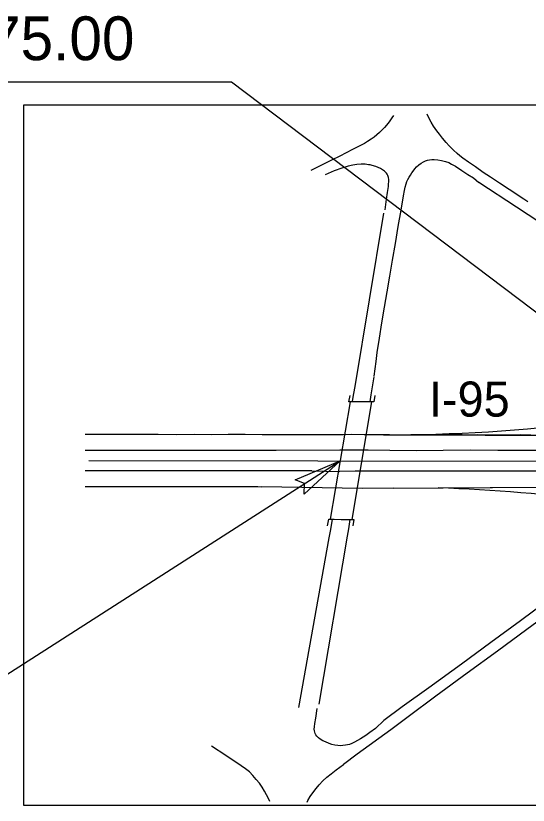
# Model space of a CAD drawing. Extents: x 2241278 to 2254132, y 649924 to 670434.
# Drawn here: x 2247319 to 2248087, y 662535 to 663719 of the extents above; entities that cross this region are included whole.
import ezdxf

# ---------------------------------------------------------------- set-up
doc = ezdxf.new("R2010")
doc.units = 0
for name, color, linetype in [('Pattern 4', 7, 'Continuous'), ('Pattern 6', 7, 'Continuous'), ('Prop DSN Text', 7, 'Continuous'), ('Prop Horizontal Alignment', 7, 'Continuous'), ('Prop RDY Alternate Text Yellow', 7, 'Continuous'), ('Prop Shade Heavy', 7, 'Continuous'), ('Prop Terminator CELL', 7, 'Continuous')]:
    doc.layers.add(name, color=color, linetype=linetype)

msp = doc.modelspace()

# ---------------------------------------------------------------- linework, layer by layer
at = {"layer": 'Pattern 4'}
for p, q in [((2248005.2, 663476.3), (2248013.5, 663469.4)), ((2247709.4, 663067.8), (2247804.9, 663068.4)), ((2247762.8, 663036.7), (2247804.9, 663036.1)), ((2247858.5, 662650.7), (2247870.8, 662662.3))]:
    msp.add_line(p, q, dxfattribs=at)
for points in [[(2247885.4, 663569.9), (2247883.1, 663566.4), (2247878.8, 663560.1), (2247874.9, 663555.4), (2247871.7, 663551.5), (2247867.8, 663547.5), (2247864.3, 663544), (2247860.6, 663540.6), (2247856.4, 663537.3), (2247852, 663534.1), (2247846.5, 663530.6), (2247842, 663527.9), (2247823.9, 663518.6), (2247804.8, 663508.9), (2247792.6, 663503), (2247782.4, 663498), (2247770.4, 663492), (2247761.3, 663487.5)], [(2248086.8, 663440.4), (2248080.8, 663444.4), (2248059.1, 663458.6), (2248044.5, 663468.3), (2248030.8, 663477.3), (2248020.1, 663484.5), (2248008.5, 663492.6), (2247998, 663499.7), (2247989.6, 663505.6), (2247984.9, 663509.2), (2247980.7, 663512.9), (2247975.2, 663518), (2247968.9, 663524.3), (2247964.2, 663529.5), (2247959.1, 663535.7), (2247954.2, 663541.5), (2247950.3, 663546.8), (2247945.5, 663553.8), (2247942, 663559.5), (2247938.9, 663565.4), (2247936.1, 663571.5), (2247936, 663571.8)], [(2247856.6, 663178.7), (2247859.5, 663200.9), (2247860.8, 663214.2), (2247864.2, 663236), (2247868.1, 663258.9), (2247872, 663282.4), (2247876, 663305.1), (2247879.9, 663328.7), (2247884.1, 663352.7), (2247888.2, 663377.9), (2247892.6, 663403.1), (2247896.9, 663427.8), (2247900.6, 663449.3), (2247902.1, 663457.5), (2247902.9, 663462.2), (2247904.2, 663467.3), (2247905.6, 663470.9), (2247907.1, 663474), (2247908.8, 663477.1), (2247910.7, 663480.5), (2247912.8, 663483.7), (2247915, 663486.4), (2247917.3, 663489.7), (2247920.1, 663492.9), (2247923.2, 663495.8), (2247926.7, 663498.3), (2247930.5, 663500.5), (2247933.3, 663501.9), (2247936.2, 663502.9), (2247939.4, 663503.5), (2247942.8, 663503.8), (2247946.2, 663503.8), (2247951.8, 663503.2), (2247957.3, 663502.1), (2247963.6, 663500.9), (2247968.4, 663499.1), (2247972.6, 663497), (2247978.2, 663493.9), (2247987.8, 663487.4), (2247997.1, 663481.1), (2248005.2, 663476.3)], [(2247872.7, 663428.5), (2247875, 663444.3), (2247876.5, 663454.2), (2247877.7, 663463.2), (2247878.1, 663467), (2247878.3, 663471), (2247878.3, 663473.8), (2247877.7, 663476.7), (2247876.9, 663479.6), (2247875.9, 663481.8), (2247875, 663483.1), (2247874, 663484.2), (2247871.8, 663486.5), (2247868.9, 663488.5), (2247865.9, 663490.2), (2247862.2, 663491.9), (2247858.9, 663493.1), (2247853.3, 663494.9), (2247850.3, 663495.6), (2247847.8, 663496), (2247842.8, 663496.8), (2247836.9, 663496.9), (2247830.6, 663496.4), (2247824.3, 663495.4), (2247817.2, 663493.7), (2247808.1, 663491), (2247796.3, 663486.8), (2247782.7, 663481)], [(2248329.4, 663262.5), (2248284.1, 663292), (2248247.5, 663316), (2248175.8, 663363.1), (2248120.9, 663398.9), (2248069.7, 663432.4), (2248013.5, 663469.4)], [(2247870.4, 663423.3), (2247827.2, 663163.3), (2247825.5, 663152.9), (2247823.6, 663141.4)], [(2247850.2, 663140.4), (2247851.9, 663151), (2247853.9, 663162.8), (2247856.4, 663177.8)], [(2247807.9, 663091.1), (2247784.8, 663091.1), (2247761.5, 663091.1), (2247738, 663091.1), (2247713.3, 663091.1), (2247688.4, 663091.1), (2247663, 663091.2), (2247637.6, 663091.2), (2247612.2, 663091.1), (2247586.3, 663091.2), (2247559.6, 663091.1), (2247532.4, 663091.3), (2247504.8, 663091.3), (2247475.9, 663091.3), (2247446.7, 663091.3), (2247423, 663091.2)], [(2247810.3, 663091.1), (2247807.9, 663091.1)], [(2248091.3, 663090.5), (2248076.6, 663090.7), (2248064.7, 663090.6), (2248055.2, 663090.3), (2248047, 663090.5), (2248033.8, 663090.5), (2248023, 663090.6), (2248011.1, 663090.7), (2248001.4, 663090.6), (2247988.3, 663090.7), (2247977.7, 663090.9), (2247969.5, 663090.8), (2247955.6, 663090.8), (2247940.8, 663090.9), (2247925.9, 663090.8), (2247911.6, 663091), (2247897.8, 663090.6), (2247879.4, 663090.8), (2247858.8, 663090.7), (2247841.2, 663091.1), (2247822.3, 663091.3), (2247810.3, 663091.1)], [(2247423.1, 663067.9), (2247443.6, 663067.8), (2247476.3, 663067.9), (2247509.2, 663067.9), (2247542.1, 663068), (2247575.5, 663067.8), (2247609.3, 663067.8), (2247642.9, 663067.8), (2247676.2, 663067.9), (2247709.4, 663067.8)], [(2247804.9, 663068.4), (2247847.2, 663068.4), (2247879.7, 663067.8), (2247919.8, 663067.6), (2247960.1, 663068.1), (2248001.5, 663068.2), (2248042, 663067.9), (2248081, 663067.9), (2248120.5, 663067.8)], [(2247762.8, 663036.7), (2247728.3, 663036.8), (2247698.4, 663036.8), (2247667.2, 663036.8), (2247636.6, 663036.8), (2247606.5, 663036.8), (2247574.8, 663037), (2247543.3, 663036.9), (2247510.7, 663037), (2247481.5, 663037), (2247453.4, 663037.1), (2247431.9, 663037), (2247423, 663037.1)], [(2248112.1, 663036.5), (2248065.5, 663036.6), (2248029.4, 663036.6), (2247990.8, 663036.4), (2247952.3, 663036.6), (2247910.4, 663036.3), (2247868.7, 663036.5), (2247827.7, 663036.5), (2247804.9, 663036.1)], [(2247422.9, 663013.5), (2247431.7, 663013.5), (2247466.8, 663013.4), (2247501.9, 663013.3), (2247537.2, 663013.3), (2247572.2, 663013.2), (2247607.9, 663013.4), (2247643.9, 663013.3), (2247681.7, 663013.3), (2247687.6, 663012.7)], [(2247885.2, 663010.9), (2247839, 663010.3), (2247687.6, 663012.7)], [(2247885.2, 663010.9), (2248108.4, 663012.5), (2248343.7, 663010.3)], [(2247793.2, 662964.2), (2247790.7, 662948.8), (2247788.6, 662936.2), (2247743, 662682.1)], [(2247773.8, 662687.1), (2247816.4, 662939), (2247818.2, 662949.7), (2247820.5, 662964)], [(2248190.7, 662875.9), (2248128.2, 662830.3), (2248085.6, 662798.9), (2248041.3, 662766.6), (2247996.1, 662733.5), (2247949.1, 662698.8), (2247907.2, 662667.9), (2247881.2, 662648.5), (2247830.7, 662611.8), (2247810.3, 662596.7)], [(2248168.8, 662880.1), (2248117.1, 662842.2), (2248076, 662811.9), (2248031.2, 662779.3), (2247987.4, 662747.2), (2247938.6, 662711.6), (2247898.5, 662682.8), (2247870.8, 662662.3)], [(2247858.5, 662650.7), (2247849.7, 662644.4), (2247843.9, 662640.1), (2247840, 662637.5), (2247835.8, 662634.9), (2247831.6, 662632.4), (2247826.7, 662629.8), (2247823, 662628.1), (2247819.3, 662626.7), (2247816.5, 662625.9), (2247813.5, 662625.3), (2247809.5, 662624.8), (2247805.5, 662624.6), (2247801.7, 662624.8), (2247797.3, 662625.6), (2247792.9, 662626.7), (2247789, 662628), (2247783.2, 662630.3), (2247779.4, 662632), (2247775.6, 662634.3), (2247772.7, 662636.6), (2247770.2, 662639.2), (2247768.8, 662641.1), (2247767.8, 662643.2), (2247767.2, 662644.9), (2247766.8, 662646.8), (2247766.6, 662649.5), (2247766.8, 662653), (2247767.5, 662658.1), (2247769, 662666.2), (2247771, 662680.3)], [(2247699.7, 662541.1), (2247697.8, 662545.3), (2247694.9, 662550.8), (2247691.8, 662556.6), (2247688.3, 662562.4), (2247684.2, 662568.3), (2247679.5, 662574.2), (2247674.5, 662580.1), (2247669.2, 662585.3), (2247663.4, 662590), (2247656.8, 662594.7), (2247633.7, 662610.2), (2247612.5, 662624)], [(2247755.7, 662540), (2247757, 662542.6), (2247760.6, 662548.3), (2247764.6, 662554.2), (2247769.2, 662560.3), (2247774, 662566.2), (2247779.4, 662571.8), (2247785.3, 662577.3), (2247791.8, 662582.6), (2247799.3, 662588.4), (2247810.3, 662596.7)]]:
    msp.add_lwpolyline(points, dxfattribs=at)
at = {"layer": 'Pattern 6'}
for points in [[(2247857.4, 663150), (2247855.9, 663140.3), (2247850.1, 663140.3), (2247849.6, 663140.3), (2247836.9, 663140.3), (2247823.9, 663140.3), (2247823.3, 663140.3), (2247818.4, 663140.3), (2247820.2, 663150)], [(2247791.1, 662964.4), (2247821, 663140.2)], [(2247852.6, 663140.2), (2247822.9, 662964.1)], [(2247786.6, 662954.4), (2247788.4, 662964.2), (2247793.2, 662964.2), (2247793.7, 662964.2), (2247796.2, 662964.2), (2247807, 662964.1), (2247817.7, 662964), (2247820, 662964), (2247820.5, 662964), (2247820.7, 662964), (2247825.9, 662964), (2247824.3, 662954.6)]]:
    msp.add_lwpolyline(points, dxfattribs=at)
at = {"layer": 'Prop DSN Text'}
for p, q in [((2251198.4, 663585.5), (2247330.5, 663585.4)), ((2247330.5, 663585.4), (2247330.5, 662535.4)), ((2247330.5, 662535.4), (2251198.4, 662535.4))]:
    msp.add_line(p, q, dxfattribs=at)
at = {"layer": 'Prop Horizontal Alignment'}
msp.add_line((2247428.2, 663052.4), (2250138, 663049.1), dxfattribs=at)
at = {"layer": 'Prop RDY Alternate Text Yellow'}
for p, q in [((2245682.7, 663620.4), (2247642.6, 663620.4)), ((2247642.6, 663620.4), (2248395.3, 663051.2)), ((2247175, 662647.8), (2247805.3, 663051.9))]:
    msp.add_line(p, q, dxfattribs=at)
at = {"layer": 'Prop Shade Heavy'}
msp.add_line((2247952.4, 663011.4), (2248108.4, 663012.5), dxfattribs=at)
msp.add_lwpolyline([(2247870.3, 663090.8), (2247955.6, 663090.8), (2248023, 663090.6), (2248139.1, 663090.5)], dxfattribs=at)
for centre, start, end in [((2247873.3, 665578.8), 269.9322, 277.1844), ((2247867.3, 660524.8), 82.3255, 88.0399)]:
    msp.add_arc(centre, 2488, start, end, dxfattribs=at)
at = {"layer": 'Prop Terminator CELL'}
msp.add_lwpolyline([(2247738, 663023.5), (2247805.3, 663051.9), (2247751.2, 663002.1), (2247752.1, 663017.8)], close=True, dxfattribs=at)

# ---------------------------------------------------------------- texts
at = {"layer": 'Prop RDY Alternate Text Yellow'}
for s, height, p in [('BEGIN TIP PROJECT I-3318BB -L- 15+75.00', 65.626, (2245714.1, 663652.7)), ('I-95', 52.59, (2247938.5, 663118.2))]:
    msp.add_text(s, height=height, dxfattribs=at).set_placement(p)

doc.saveas('drawing.dxf')
